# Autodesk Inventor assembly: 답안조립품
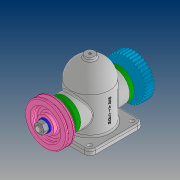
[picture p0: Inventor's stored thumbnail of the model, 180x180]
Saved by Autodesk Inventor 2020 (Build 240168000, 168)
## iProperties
Created: 2021-08
Part Number: 답안조립품
Document SubType Name: Assembly
Designer: PC312-
Author: PC312-
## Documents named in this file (14)
- C:\Users\PC312-\Desktop\710809V1002\답안조립품.iam
- C:\Users\PC312-\Desktop\710809V1002\본체.ipt
- C:\Users\PC312-\Desktop\710809V1002\축.ipt
- C:\Users\PC312-\Desktop\710809V1002\베어링 6203.ipt
- C:\Users\PC312-\Desktop\710809V1002\부시.ipt
- C:\Users\PC312-\Desktop\710809V1002\커버.ipt
- C:\Users\PC312-\Desktop\710809V1002\오일 실 26 38 8.ipt
- C:\Users\PC312-\Desktop\710809V1002\볼트 M4.ipt
- C:\Users\PC312-\Desktop\710809V1002\키 5x5x12.ipt
- C:\Users\PC312-\Desktop\710809V1002\V-벨트풀리.ipt
- V-벨트풀리.ipt
- C:\Users\PC312-\Desktop\710809V1002\스퍼기어.ipt
- C:\Users\PC312-\Desktop\710809V1002\와셔 12x24.ipt
- C:\Users\PC312-\Desktop\710809V1002\너트 M12x1.25.ipt
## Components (1 placed, 1 different names)
1. V-벨트풀리:1
